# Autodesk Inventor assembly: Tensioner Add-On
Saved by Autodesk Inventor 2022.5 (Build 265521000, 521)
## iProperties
Created: 2025-01
Part Number: Tensioner Add-On
Document SubType Name: Assembly
Designer: AdminForWorker
Title: Tensioner Add-On v12
Author: AdminForWorker
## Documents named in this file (4)
- c:\worker\convert-fusion-r06-cosv3\tmp\job-1\60\temp\files\c919e9fb-1ec6-4dd5-a926-e426b13daf31\863a88e3-ed3b-40a8-af2c-889c02c76b92.iam
- c:\worker\convert-fusion-r06-cosv3\tmp\job-1\60\temp\files\c919e9fb-1ec6-4dd5-a926-e426b13daf31\Bearing 4_12 ID_OD v1.ipt
- c:\worker\convert-fusion-r06-cosv3\tmp\job-1\60\temp\files\c919e9fb-1ec6-4dd5-a926-e426b13daf31\Tension Roller v9.ipt
- c:\worker\convert-fusion-r06-cosv3\tmp\job-1\60\temp\files\c919e9fb-1ec6-4dd5-a926-e426b13daf31\Part6.ipt
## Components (4 placed, 3 different names)
1. Bearing 4/12 ID/OD v1:1
2. Bearing 4/12 ID/OD v1:2
3. Tension Roller v9:1
4. Part6
